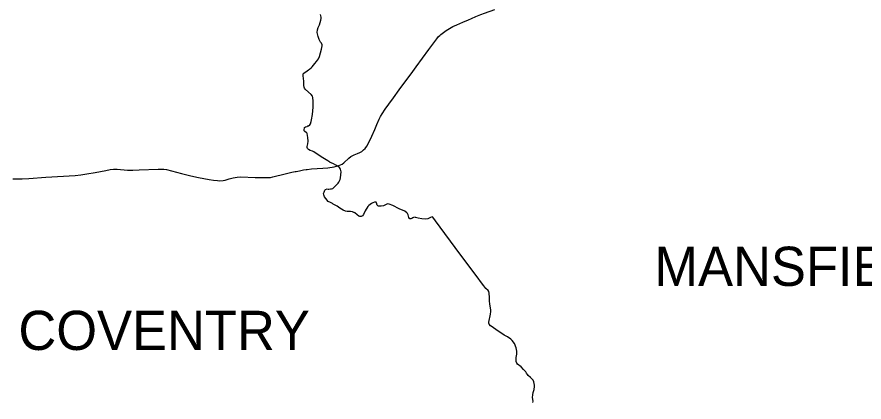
# Model space of a CAD drawing. Extents: x 0 to 2603, y -226 to 830.
# Drawn here: x 258.1 to 287.25, y 640.19 to 653.45 of the extents above; entities that cross this region are included whole.
import ezdxf

# ---------------------------------------------------------------- set-up
doc = ezdxf.new("R2010")
doc.units = 0
for name, color, linetype in [('CT_TSH_Map_Districts', 7, 'Continuous'), ('CT_TSH_Map_Town_Limits', 7, 'Continuous'), ('CT_TSH_Map_Town_Text', 7, 'Continuous'), ('CT_TSH_Map_US_and_State_Routes', 7, 'Continuous')]:
    doc.layers.add(name, color=color, linetype=linetype)

msp = doc.modelspace()

# ---------------------------------------------------------------- linework, layer by layer
at = {"layer": 'CT_TSH_Map_Districts'}
for points in [[(268.463, 653.089), (268.51, 653.175), (268.554, 653.333), (268.563, 653.397), (268.561, 653.446), (268.542, 653.535)], [(269.691, 646.717), (269.649, 646.733), (269.581, 646.746), (269.463, 646.745), (269.407, 646.758), (269.318, 646.796), (269.207, 646.863), (269.162, 646.897), (269.117, 646.932), (268.979, 647.004), (268.954, 647.021), (268.883, 647.058), (268.81, 647.099), (268.724, 647.197), (268.686, 647.252), (268.658, 647.322), (268.651, 647.364), (268.664, 647.415), (268.69, 647.479), (268.716, 647.508), (268.77, 647.525), (268.809, 647.522), (268.829, 647.518), (268.889, 647.526), (268.918, 647.527), (268.964, 647.547), (269.154, 647.72), (269.177, 647.757), (269.215, 647.853), (269.234, 647.913), (269.255, 648.113), (269.248, 648.163), (269.23, 648.212), (269.194, 648.264), (269.164, 648.291), (269.093, 648.337), (268.972, 648.397), (268.877, 648.442), (268.864, 648.452), (268.79, 648.494), (268.627, 648.595), (268.494, 648.673), (268.317, 648.808), (268.272, 648.829), (268.189, 648.851), (268.132, 648.882), (268.099, 648.922), (268.087, 648.955), (268.086, 648.986), (268.112, 649.083), (268.118, 649.177), (268.112, 649.296), (268.09, 649.431), (268.078, 649.46), (268.055, 649.475), (268.001, 649.507), (267.984, 649.53), (267.976, 649.558), (267.987, 649.63), (267.997, 649.647), (268.026, 649.663), (268.089, 649.679), (268.112, 649.694), (268.135, 649.702), (268.177, 649.733), (268.199, 649.763), (268.222, 649.845), (268.232, 649.908), (268.264, 650.085), (268.289, 650.346), (268.293, 650.548), (268.282, 650.676), (268.267, 650.72), (268.217, 650.782), (268.032, 650.95), (267.993, 651.001), (267.979, 651.03), (267.967, 651.083), (267.965, 651.234), (267.943, 651.421), (267.947, 651.484), (267.969, 651.514), (268.079, 651.595), (268.125, 651.626), (268.168, 651.648), (268.217, 651.699), (268.251, 651.725), (268.352, 651.846), (268.406, 651.92), (268.476, 652.01), (268.512, 652.081), (268.576, 652.34), (268.6, 652.452), (268.6, 652.491), (268.574, 652.542), (268.543, 652.58), (268.496, 652.672), (268.463, 652.774), (268.433, 652.918), (268.436, 653.008), (268.463, 653.089)], [(275.847, 640.442), (275.86, 640.515), (275.899, 640.625), (275.91, 640.723), (275.908, 640.768), (275.884, 640.885), (275.861, 640.94), (275.844, 640.97), (275.787, 641.02), (275.774, 641.036), (275.694, 641.108), (275.672, 641.141), (275.638, 641.181), (275.605, 641.232), (275.532, 641.311), (275.447, 641.396), (275.323, 641.499), (275.299, 641.532), (275.281, 641.583), (275.273, 641.652), (275.275, 641.722), (275.295, 641.842), (275.299, 641.94), (275.276, 642.06), (275.215, 642.204), (275.14, 642.311), (275.088, 642.359), (274.978, 642.433), (274.865, 642.491), (274.679, 642.618), (274.624, 642.649), (274.447, 642.776), (274.389, 642.817), (274.343, 642.872), (274.332, 642.91), (274.333, 642.941), (274.395, 643.214), (274.409, 643.307), (274.41, 643.315), (274.41, 643.359), (274.367, 643.561), (274.357, 643.672), (274.356, 643.788), (274.345, 643.934), (274.331, 643.991), (274.308, 644.032), (274.237, 644.104), (274.162, 644.192), (274.048, 644.342), (273.973, 644.45), (273.343, 645.292), (272.506, 646.427), (272.409, 646.556), (272.382, 646.562), (272.333, 646.545), (272.242, 646.501), (272.146, 646.487), (272.025, 646.497), (271.909, 646.52), (271.809, 646.545), (271.796, 646.552), (271.748, 646.547), (271.719, 646.535), (271.691, 646.508), (271.648, 646.493), (271.617, 646.495), (271.603, 646.509), (271.585, 646.546), (271.565, 646.631), (271.541, 646.68), (271.519, 646.706), (271.442, 646.759), (271.251, 646.846), (271.032, 646.954), (270.907, 647.002), (270.862, 647.009), (270.825, 647.002), (270.709, 646.949), (270.63, 646.933), (270.567, 646.929), (270.535, 646.932), (270.518, 646.94), (270.494, 646.964), (270.474, 647.048), (270.459, 647.067), (270.441, 647.072), (270.407, 647.071), (270.343, 647.049), (270.293, 647.022), (270.202, 646.953), (270.174, 646.921), (270.082, 646.773), (270.022, 646.645), (269.985, 646.599), (269.938, 646.579), (269.892, 646.58), (269.86, 646.594), (269.809, 646.631), (269.72, 646.707), (269.705, 646.716), (269.691, 646.717)], [(275.856, 640.171), (275.857, 640.221), (275.836, 640.348), (275.847, 640.442)]]:
    msp.add_lwpolyline(points, dxfattribs=at)
at = {"layer": 'CT_TSH_Map_Town_Limits'}
for points in [[(268.463, 653.089), (268.51, 653.175), (268.554, 653.333), (268.563, 653.397), (268.561, 653.446), (268.542, 653.535)], [(269.691, 646.717), (269.649, 646.733), (269.581, 646.746), (269.463, 646.745), (269.407, 646.758), (269.318, 646.796), (269.207, 646.863), (269.162, 646.897), (269.117, 646.932), (268.979, 647.004), (268.954, 647.021), (268.883, 647.058), (268.81, 647.099), (268.724, 647.197), (268.686, 647.252), (268.658, 647.322), (268.651, 647.364), (268.664, 647.415), (268.69, 647.479), (268.716, 647.508), (268.77, 647.525), (268.809, 647.522), (268.829, 647.518), (268.889, 647.526), (268.918, 647.527), (268.964, 647.547), (269.154, 647.72), (269.177, 647.757), (269.215, 647.853), (269.234, 647.913), (269.255, 648.113), (269.248, 648.163), (269.23, 648.212), (269.194, 648.264), (269.164, 648.291), (269.093, 648.337), (268.972, 648.397), (268.877, 648.442), (268.864, 648.452), (268.79, 648.494), (268.627, 648.595), (268.494, 648.673), (268.317, 648.808), (268.272, 648.829), (268.189, 648.851), (268.132, 648.882), (268.099, 648.922), (268.087, 648.955), (268.086, 648.986), (268.112, 649.083), (268.118, 649.177), (268.112, 649.296), (268.09, 649.431), (268.078, 649.46), (268.055, 649.475), (268.001, 649.507), (267.984, 649.53), (267.976, 649.558), (267.987, 649.63), (267.997, 649.647), (268.026, 649.663), (268.089, 649.679), (268.112, 649.694), (268.135, 649.702), (268.177, 649.733), (268.199, 649.763), (268.222, 649.845), (268.232, 649.908), (268.264, 650.085), (268.289, 650.346), (268.293, 650.548), (268.282, 650.676), (268.267, 650.72), (268.217, 650.782), (268.032, 650.95), (267.993, 651.001), (267.979, 651.03), (267.967, 651.083), (267.965, 651.234), (267.943, 651.421), (267.947, 651.484), (267.969, 651.514), (268.079, 651.595), (268.125, 651.626), (268.168, 651.648), (268.217, 651.699), (268.251, 651.725), (268.352, 651.846), (268.406, 651.92), (268.476, 652.01), (268.512, 652.081), (268.576, 652.34), (268.6, 652.452), (268.6, 652.491), (268.574, 652.542), (268.543, 652.58), (268.496, 652.672), (268.463, 652.774), (268.433, 652.918), (268.436, 653.008), (268.463, 653.089)], [(275.847, 640.442), (275.86, 640.515), (275.899, 640.625), (275.91, 640.723), (275.908, 640.768), (275.884, 640.885), (275.861, 640.94), (275.844, 640.97), (275.787, 641.02), (275.774, 641.036), (275.694, 641.108), (275.672, 641.141), (275.638, 641.181), (275.605, 641.232), (275.532, 641.311), (275.447, 641.396), (275.323, 641.499), (275.299, 641.532), (275.281, 641.583), (275.273, 641.652), (275.275, 641.722), (275.295, 641.842), (275.299, 641.94), (275.276, 642.06), (275.215, 642.204), (275.14, 642.311), (275.088, 642.359), (274.978, 642.433), (274.865, 642.491), (274.679, 642.618), (274.624, 642.649), (274.447, 642.776), (274.389, 642.817), (274.343, 642.872), (274.332, 642.91), (274.333, 642.941), (274.395, 643.214), (274.409, 643.307), (274.41, 643.315), (274.41, 643.359), (274.367, 643.561), (274.357, 643.672), (274.356, 643.788), (274.345, 643.934), (274.331, 643.991), (274.308, 644.032), (274.237, 644.104), (274.162, 644.192), (274.048, 644.342), (273.973, 644.45), (273.343, 645.292), (272.506, 646.427), (272.409, 646.556), (272.382, 646.562), (272.333, 646.545), (272.242, 646.501), (272.146, 646.487), (272.025, 646.497), (271.909, 646.52), (271.809, 646.545), (271.796, 646.552), (271.748, 646.547), (271.719, 646.535), (271.691, 646.508), (271.648, 646.493), (271.617, 646.495), (271.603, 646.509), (271.585, 646.546), (271.565, 646.631), (271.541, 646.68), (271.519, 646.706), (271.442, 646.759), (271.251, 646.846), (271.032, 646.954), (270.907, 647.002), (270.862, 647.009), (270.825, 647.002), (270.709, 646.949), (270.63, 646.933), (270.567, 646.929), (270.535, 646.932), (270.518, 646.94), (270.494, 646.964), (270.474, 647.048), (270.459, 647.067), (270.441, 647.072), (270.407, 647.071), (270.343, 647.049), (270.293, 647.022), (270.202, 646.953), (270.174, 646.921), (270.082, 646.773), (270.022, 646.645), (269.985, 646.599), (269.938, 646.579), (269.892, 646.58), (269.86, 646.594), (269.809, 646.631), (269.72, 646.707), (269.705, 646.716), (269.691, 646.717)], [(275.856, 640.171), (275.857, 640.221), (275.836, 640.348), (275.847, 640.442)]]:
    msp.add_lwpolyline(points, dxfattribs=at)
at = {"layer": 'CT_TSH_Map_US_and_State_Routes'}
for p, q in [((273.238, 653.18), (273.441, 653.266)), ((272.273, 652.327), (272.473, 652.6)), ((271.84, 651.732), (272.273, 652.327)), ((271.663, 651.492), (271.84, 651.732)), ((271.255, 650.94), (271.52, 651.299)), ((271.52, 651.299), (271.663, 651.492)), ((270.768, 650.273), (270.892, 650.448)), ((270.483, 649.75), (270.561, 649.928)), ((262.088, 648.175), (262.304, 648.18)), ((262.304, 648.18), (262.951, 648.209)), ((267.674, 648.123), (267.711, 648.131)), ((268.23, 648.217), (268.62, 648.247)), ((269.014, 648.283), (269.176, 648.328)), ((257.955, 647.87), (258.272, 647.875)), ((258.272, 647.875), (258.509, 647.89)), ((258.509, 647.89), (259.087, 647.927)), ((259.087, 647.927), (260.096, 647.989))]:
    msp.add_line(p, q, dxfattribs=at)
for points in [[(273.441, 653.266), (273.636, 653.348), (273.745, 653.397), (273.89, 653.459), (274.06, 653.529), (274.188, 653.581), (274.548, 653.708)], [(272.869, 652.98), (272.985, 653.052), (273.103, 653.117), (273.238, 653.18)], [(272.473, 652.6), (272.543, 652.693), (272.607, 652.771), (272.648, 652.815), (272.685, 652.848), (272.729, 652.883), (272.869, 652.98)], [(270.892, 650.448), (271.05, 650.665), (271.255, 650.94)], [(270.561, 649.928), (270.605, 650.016), (270.661, 650.112), (270.768, 650.273)], [(270.313, 649.345), (270.41, 649.572), (270.483, 649.75)], [(270.028, 648.871), (270.085, 648.922), (270.137, 648.995), (270.206, 649.12), (270.313, 649.345)], [(269.517, 648.589), (269.584, 648.641), (269.653, 648.683), (269.697, 648.7), (269.811, 648.742), (269.9, 648.786), (269.961, 648.821), (270.028, 648.871)], [(269.176, 648.328), (269.236, 648.354), (269.287, 648.384), (269.341, 648.42), (269.517, 648.589)], [(260.096, 647.989), (260.3, 648.011), (260.504, 648.041), (260.784, 648.091)], [(260.784, 648.091), (260.973, 648.13), (261.152, 648.163), (261.305, 648.192), (261.425, 648.202), (261.547, 648.202), (261.907, 648.178), (262.088, 648.175)], [(262.951, 648.209), (263.063, 648.21), (263.15, 648.21), (263.246, 648.193), (263.761, 648.056), (264.079, 647.979), (264.341, 647.919), (264.71, 647.849), (264.856, 647.825), (265, 647.815)], [(266.905, 647.939), (267.328, 648.043), (267.551, 648.1), (267.674, 648.123)], [(267.711, 648.131), (267.823, 648.155), (267.958, 648.18), (268.05, 648.195)], [(268.05, 648.195), (268.081, 648.2), (268.23, 648.217)], [(268.62, 648.247), (268.8, 648.256), (269.014, 648.283)], [(265, 647.815), (265.08, 647.808), (265.189, 647.817), (265.264, 647.83), (265.402, 647.869), (265.543, 647.911), (265.675, 647.931), (265.799, 647.939), (266.295, 647.926), (266.663, 647.921), (266.826, 647.926), (266.905, 647.939)]]:
    msp.add_lwpolyline(points, dxfattribs=at)

# ---------------------------------------------------------------- texts
at = {"layer": 'CT_TSH_Map_Town_Text'}
for s, p in [('MANSFIELD', (280.033, 644.188)), ('COVENTRY', (258.147, 641.982))]:
    msp.add_text(s, height=1.35, dxfattribs=at).set_placement(p)

doc.saveas('drawing.dxf')
